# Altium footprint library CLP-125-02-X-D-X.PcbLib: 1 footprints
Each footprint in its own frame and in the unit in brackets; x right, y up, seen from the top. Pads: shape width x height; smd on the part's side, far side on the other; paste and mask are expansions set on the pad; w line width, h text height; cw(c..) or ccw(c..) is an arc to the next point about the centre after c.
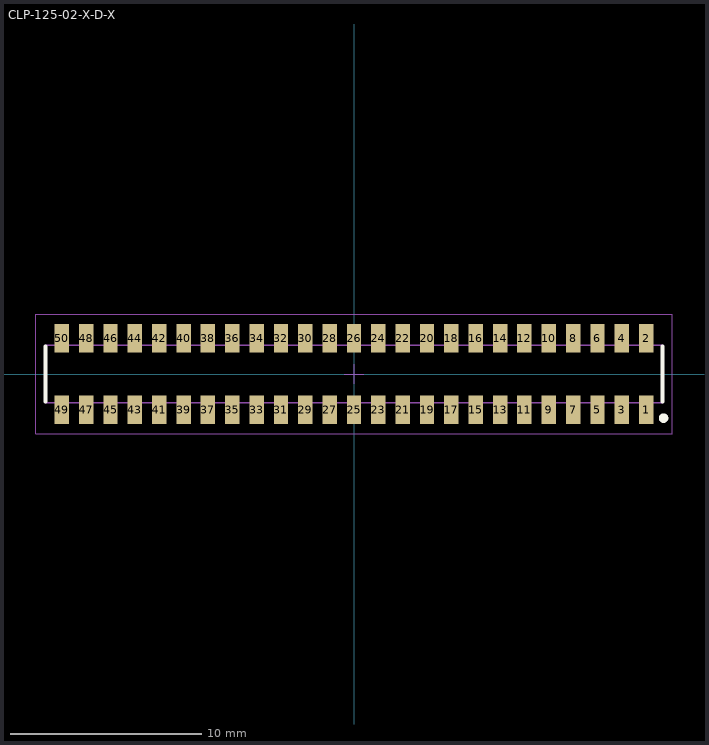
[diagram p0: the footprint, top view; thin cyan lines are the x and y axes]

## CLP-125-02-X-D-X [mm] "1.27mm pitch, 50 pin, socket strip; low profile"
height 2.26
pads (50):
  rect 0.75x1.5 smd mask+0: 1(15.24,-1.87) 2(15.24,1.87) 3(13.97,-1.87) 4(13.97,1.87) 5(12.7,-1.87) 6(12.7,1.87) 7(11.43,-1.87) 8(11.43,1.87) 9(10.16,-1.87) 10(10.16,1.87) 11(8.89,-1.87) 12(8.89,1.87) 13(7.62,-1.87) 14(7.62,1.87) 15(6.35,-1.87) 16(6.35,1.87) 17(5.08,-1.87) 18(5.08,1.87) 19(3.81,-1.87) 20(3.81,1.87) 21(2.54,-1.87) 22(2.54,1.87) 23(1.27,-1.87) 24(1.27,1.87) 25(0,-1.87) 26(0,1.87) 27(-1.27,-1.87) 28(-1.27,1.87) 29(-2.54,-1.87) 30(-2.54,1.87) 31(-3.81,-1.87) 32(-3.81,1.87) 33(-5.08,-1.87) 34(-5.08,1.87) 35(-6.35,-1.87) 36(-6.35,1.87) 37(-7.62,-1.87) 38(-7.62,1.87) 39(-8.89,-1.87) 40(-8.89,1.87) 41(-10.16,-1.87) 42(-10.16,1.87) 43(-11.43,-1.87) 44(-11.43,1.87) 45(-12.7,-1.87) 46(-12.7,1.87) 47(-13.97,-1.87) 48(-13.97,1.87) 49(-15.24,-1.87) 50(-15.24,1.87)
Top Overlay:
  circle w0.25: c16.15,-2.3 r0.125
  lines w0.2: -16.1,-1.45 -16.1,1.45 ; 16.1,-1.45 16.1,1.45
Mechanical 12:
  lines w0.001: -16.1,-1.5 -16.1,1.5 16.1,1.5 16.1,-1.5 -16.1,-1.5
Mechanical 13:
  lines w0.1: -16.1,-1.5 -16.1,1.5 16.1,1.5 16.1,-1.5 -16.1,-1.5
  text ".Designator" at 0.254,0.254 h1.52
Mechanical 15:
  lines w0.05: -0.5,0 0.5,0 ; 0,-0.5 0,0.5 ; -16.599,-3.111 -16.599,3.111 16.599,3.111 16.599,-3.111 -16.599,-3.111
